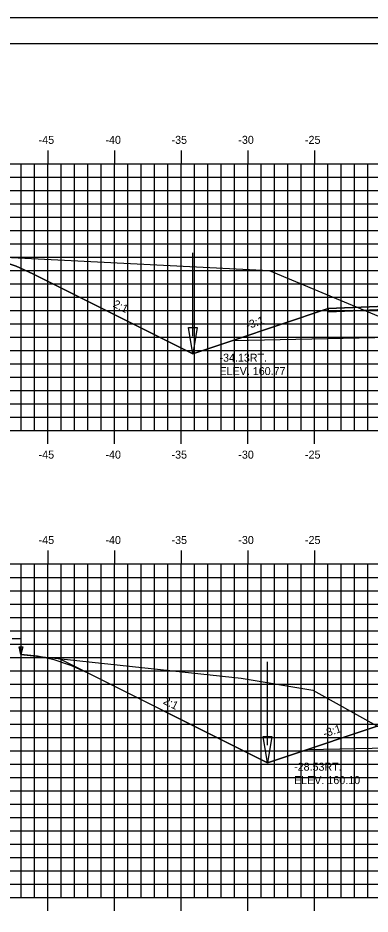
# Model space of a CAD drawing. Extents: x 1141424 to 1141594, y 608981 to 609091.
# Drawn here: x 1141460 to 1141486.4, y 609024.1 to 609091.3 of the extents above; entities that cross this region are included whole.
import ezdxf

# ---------------------------------------------------------------- set-up
doc = ezdxf.new("R2010")
doc.units = 0
for name, color, linetype in [('ANNOTATION', 7, 'Continuous'), ('BORDER', 7, 'Continuous'), ('D_Drainage_Ditch_Line', 7, 'Continuous'), ('D_Roadway_Edge_Shoulder', 7, 'Continuous'), ('D_Roadway_SlopeLines', 7, 'Continuous'), ('D_Roadway_SubGrade', 7, 'Continuous'), ('D_Text_Standard', 7, 'Continuous'), ('H_V ANNOTATION', 7, 'Continuous'), ('MAJOR', 7, 'Continuous'), ('MINOR', 7, 'Continuous'), ('PLOT BOUNDARY', 7, 'Continuous'), ('S_Roadway_Centerline', 7, 'Continuous')]:
    doc.layers.add(name, color=color, linetype=linetype)

msp = doc.modelspace()

# ---------------------------------------------------------------- linework, layer by layer
for points in [[(1141456.146, 609073.465), (1141457.396, 609073.337), (1141458.646, 609073.068), (1141459.896, 609072.656), (1141461.146, 609072.102), (1141473.145, 609066.102), (1141476.145, 609067.102), (1141483.295, 609069.486), (1141483.296, 609069.486), (1141496.271, 609070.005), (1141507.271, 609070.225), (1141518.271, 609070.005), (1141522.271, 609069.845), (1141529.994, 609067.271), (1141532.994, 609066.271), (1141540.103, 609069.825), (1141541.353, 609070.365), (1141542.603, 609070.736), (1141543.853, 609070.937), (1141545.103, 609070.968)], [(1141463.072, 609043.268), (1141478.738, 609035.436), (1141481.738, 609036.436), (1141489.27, 609038.946), (1141489.271, 609038.946), (1141496.271, 609039.226), (1141507.271, 609039.446), (1141518.271, 609039.226), (1141523.862, 609039.003), (1141531.484, 609036.462), (1141534.484, 609035.462), (1141535.293, 609035.192)]]:
    msp.add_lwpolyline(points)
at = {"layer": 'BORDER'}
msp.add_lwpolyline([(1141432.271, 608984.335), (1141592.271, 608984.335), (1141592.271, 609089.335), (1141432.271, 609089.335)], close=True, dxfattribs=at)
at = {"layer": 'D_Drainage_Ditch_Line'}
for p, q in [((1141473.145, 609067.415), (1141473.145, 609073.658)), ((1141478.738, 609036.748), (1141478.738, 609042.991))]:
    msp.add_line(p, q, dxfattribs=at)
for points in [[(1141472.817, 609068.071), (1141473.473, 609068.071), (1141473.145, 609066.102)], [(1141478.41, 609037.404), (1141479.066, 609037.404), (1141478.738, 609035.436)]]:
    msp.add_lwpolyline(points, close=True, dxfattribs=at)
at = {"layer": 'D_Roadway_Edge_Shoulder'}
msp.add_lwpolyline([(1141496.271, 609070.005), (1141483.296, 609069.486), (1141483.296, 609069.236), (1141496.271, 609069.755)], close=True, dxfattribs=at)
at = {"layer": 'D_Roadway_SlopeLines'}
for points in [[(1141473.145, 609066.102), (1141461.146, 609072.102), (1141459.896, 609072.656), (1141458.646, 609073.068), (1141457.396, 609073.337), (1141456.146, 609073.465)], [(1141476.145, 609067.102), (1141473.145, 609066.102)], [(1141478.738, 609035.436), (1141465.253, 609042.178), (1141464.003, 609042.732), (1141462.753, 609043.144), (1141461.503, 609043.413), (1141460.253, 609043.541)], [(1141481.738, 609036.436), (1141478.738, 609035.436)]]:
    msp.add_lwpolyline(points, dxfattribs=at)
at = {"layer": 'D_Roadway_SubGrade'}
for points in [[(1141496.271, 609069.588), (1141496.271, 609069.755), (1141483.296, 609069.236), (1141483.296, 609069.486), (1141483.295, 609069.486), (1141476.145, 609067.102), (1141496.271, 609067.505)], [(1141496.271, 609038.81), (1141496.271, 609038.976), (1141489.271, 609038.696), (1141489.271, 609038.946), (1141489.27, 609038.946), (1141481.738, 609036.436), (1141496.271, 609036.726)]]:
    msp.add_lwpolyline(points, close=True, dxfattribs=at)
at = {"layer": 'D_Text_Standard'}
msp.add_lwpolyline([(1141460.253, 609043.541), (1141460.282, 609044.715), (1141459.602, 609044.715)], dxfattribs=at)
msp.add_lwpolyline([(1141460.253, 609043.541), (1141460.122, 609044.126), (1141460.413, 609044.119)], close=True, dxfattribs=at)
at = {"layer": 'MAJOR'}
for p, q in [((1141462.271, 609081.337), (1141462.271, 609080.335)), ((1141467.271, 609081.337), (1141467.271, 609080.335)), ((1141472.271, 609081.337), (1141472.271, 609080.335)), ((1141477.271, 609081.337), (1141477.271, 609080.335)), ((1141482.271, 609081.337), (1141482.271, 609080.335)), ((1141437.271, 609080.335), (1141577.271, 609080.335)), ((1141437.271, 609080.335), (1141577.271, 609080.335)), ((1141462.271, 609060.335), (1141462.271, 609080.335)), ((1141467.271, 609060.335), (1141467.271, 609080.335)), ((1141472.271, 609060.335), (1141472.271, 609080.335)), ((1141477.271, 609060.335), (1141477.271, 609080.335)), ((1141482.271, 609060.335), (1141482.271, 609080.335)), ((1141437.271, 609075.335), (1141577.271, 609075.335)), ((1141437.271, 609070.335), (1141577.271, 609070.335)), ((1141437.271, 609065.335), (1141577.271, 609065.335)), ((1141437.271, 609060.335), (1141577.271, 609060.335)), ((1141437.271, 609060.335), (1141577.271, 609060.335)), ((1141462.271, 609059.333), (1141462.271, 609060.335)), ((1141467.271, 609059.333), (1141467.271, 609060.335)), ((1141472.271, 609059.333), (1141472.271, 609060.335)), ((1141477.271, 609059.333), (1141477.271, 609060.335)), ((1141482.271, 609059.333), (1141482.271, 609060.335)), ((1141462.271, 609051.337), (1141462.271, 609050.335)), ((1141467.271, 609051.337), (1141467.271, 609050.335)), ((1141472.271, 609051.337), (1141472.271, 609050.335)), ((1141477.271, 609051.337), (1141477.271, 609050.335)), ((1141482.271, 609051.337), (1141482.271, 609050.335)), ((1141437.271, 609050.335), (1141577.271, 609050.335)), ((1141437.271, 609050.335), (1141577.271, 609050.335)), ((1141462.271, 609025.335), (1141462.271, 609050.335)), ((1141467.271, 609025.335), (1141467.271, 609050.335)), ((1141472.271, 609025.335), (1141472.271, 609050.335)), ((1141477.271, 609025.335), (1141477.271, 609050.335)), ((1141482.271, 609025.335), (1141482.271, 609050.335)), ((1141437.271, 609045.335), (1141577.271, 609045.335)), ((1141437.271, 609040.335), (1141577.271, 609040.335)), ((1141437.271, 609035.335), (1141577.271, 609035.335)), ((1141437.271, 609030.335), (1141577.271, 609030.335)), ((1141437.271, 609025.335), (1141577.271, 609025.335)), ((1141437.271, 609025.335), (1141577.271, 609025.335)), ((1141462.271, 609024.333), (1141462.271, 609025.335)), ((1141467.271, 609024.333), (1141467.271, 609025.335)), ((1141472.271, 609024.333), (1141472.271, 609025.335)), ((1141477.271, 609024.333), (1141477.271, 609025.335)), ((1141482.271, 609024.333), (1141482.271, 609025.335))]:
    msp.add_line(p, q, dxfattribs=at)
at = {"layer": 'MINOR'}
for p, q in [((1141460.271, 609060.335), (1141460.271, 609080.335)), ((1141461.271, 609060.335), (1141461.271, 609080.335)), ((1141463.271, 609060.335), (1141463.271, 609080.335)), ((1141464.271, 609060.335), (1141464.271, 609080.335)), ((1141465.271, 609060.335), (1141465.271, 609080.335)), ((1141466.271, 609060.335), (1141466.271, 609080.335)), ((1141468.271, 609060.335), (1141468.271, 609080.335)), ((1141469.271, 609060.335), (1141469.271, 609080.335)), ((1141470.271, 609060.335), (1141470.271, 609080.335)), ((1141471.271, 609060.335), (1141471.271, 609080.335)), ((1141473.271, 609060.335), (1141473.271, 609080.335)), ((1141474.271, 609060.335), (1141474.271, 609080.335)), ((1141475.271, 609060.335), (1141475.271, 609080.335)), ((1141476.271, 609060.335), (1141476.271, 609080.335)), ((1141478.271, 609060.335), (1141478.271, 609080.335)), ((1141479.271, 609060.335), (1141479.271, 609080.335)), ((1141480.271, 609060.335), (1141480.271, 609080.335)), ((1141481.271, 609060.335), (1141481.271, 609080.335)), ((1141483.271, 609060.335), (1141483.271, 609080.335)), ((1141484.271, 609060.335), (1141484.271, 609080.335)), ((1141485.271, 609060.335), (1141485.271, 609080.335)), ((1141486.271, 609060.335), (1141486.271, 609080.335)), ((1141437.271, 609079.335), (1141577.271, 609079.335)), ((1141437.271, 609078.335), (1141577.271, 609078.335)), ((1141437.271, 609077.335), (1141577.271, 609077.335)), ((1141437.271, 609076.335), (1141577.271, 609076.335)), ((1141437.271, 609074.335), (1141577.271, 609074.335)), ((1141437.271, 609073.335), (1141577.271, 609073.335)), ((1141437.271, 609072.335), (1141577.271, 609072.335)), ((1141437.271, 609071.335), (1141577.271, 609071.335)), ((1141437.271, 609069.335), (1141577.271, 609069.335)), ((1141437.271, 609068.335), (1141577.271, 609068.335)), ((1141437.271, 609067.335), (1141577.271, 609067.335)), ((1141437.271, 609066.335), (1141577.271, 609066.335)), ((1141437.271, 609064.335), (1141577.271, 609064.335)), ((1141437.271, 609063.335), (1141577.271, 609063.335)), ((1141437.271, 609062.335), (1141577.271, 609062.335)), ((1141437.271, 609061.335), (1141577.271, 609061.335)), ((1141460.271, 609025.335), (1141460.271, 609050.335)), ((1141461.271, 609025.335), (1141461.271, 609050.335)), ((1141463.271, 609025.335), (1141463.271, 609050.335)), ((1141464.271, 609025.335), (1141464.271, 609050.335)), ((1141465.271, 609025.335), (1141465.271, 609050.335)), ((1141466.271, 609025.335), (1141466.271, 609050.335)), ((1141468.271, 609025.335), (1141468.271, 609050.335)), ((1141469.271, 609025.335), (1141469.271, 609050.335)), ((1141470.271, 609025.335), (1141470.271, 609050.335)), ((1141471.271, 609025.335), (1141471.271, 609050.335)), ((1141473.271, 609025.335), (1141473.271, 609050.335)), ((1141474.271, 609025.335), (1141474.271, 609050.335)), ((1141475.271, 609025.335), (1141475.271, 609050.335)), ((1141476.271, 609025.335), (1141476.271, 609050.335)), ((1141478.271, 609025.335), (1141478.271, 609050.335)), ((1141479.271, 609025.335), (1141479.271, 609050.335)), ((1141480.271, 609025.335), (1141480.271, 609050.335)), ((1141481.271, 609025.335), (1141481.271, 609050.335)), ((1141483.271, 609025.335), (1141483.271, 609050.335)), ((1141484.271, 609025.335), (1141484.271, 609050.335)), ((1141485.271, 609025.335), (1141485.271, 609050.335)), ((1141486.271, 609025.335), (1141486.271, 609050.335)), ((1141437.271, 609049.335), (1141577.271, 609049.335)), ((1141437.271, 609048.335), (1141577.271, 609048.335)), ((1141437.271, 609047.335), (1141577.271, 609047.335)), ((1141437.271, 609046.335), (1141577.271, 609046.335)), ((1141437.271, 609044.335), (1141577.271, 609044.335)), ((1141437.271, 609043.335), (1141577.271, 609043.335)), ((1141437.271, 609042.335), (1141577.271, 609042.335)), ((1141437.271, 609041.335), (1141577.271, 609041.335)), ((1141437.271, 609039.335), (1141577.271, 609039.335)), ((1141437.271, 609038.335), (1141577.271, 609038.335)), ((1141437.271, 609037.335), (1141577.271, 609037.335)), ((1141437.271, 609036.335), (1141577.271, 609036.335)), ((1141437.271, 609034.335), (1141577.271, 609034.335)), ((1141437.271, 609033.335), (1141577.271, 609033.335)), ((1141437.271, 609032.335), (1141577.271, 609032.335)), ((1141437.271, 609031.335), (1141577.271, 609031.335)), ((1141437.271, 609029.335), (1141577.271, 609029.335)), ((1141437.271, 609028.335), (1141577.271, 609028.335)), ((1141437.271, 609027.335), (1141577.271, 609027.335)), ((1141437.271, 609026.335), (1141577.271, 609026.335))]:
    msp.add_line(p, q, dxfattribs=at)
at = {"layer": 'PLOT BOUNDARY'}
msp.add_lwpolyline([(1141424.178, 608981.276), (1141594.178, 608981.276), (1141594.178, 609091.276), (1141424.178, 609091.276)], close=True, dxfattribs=at)
at = {"layer": 'S_Roadway_Centerline'}
for points in [[(1141454.537, 609073.535), (1141458.051, 609073.382), (1141478.858, 609072.336), (1141491.012, 609067.255), (1141491.392, 609067.105), (1141495.226, 609067.794), (1141495.325, 609067.825), (1141495.441, 609067.836), (1141498.174, 609068.166), (1141509.012, 609068.453), (1141509.602, 609068.468), (1141519.951, 609068.08), (1141520.424, 609068.064), (1141520.58, 609068.047), (1141523.884, 609067.752), (1141523.972, 609067.719), (1141527.544, 609066.625), (1141527.941, 609066.801), (1141535.037, 609071.404), (1141544.971, 609070.972), (1141552.331, 609070.764)], [(1141460.253, 609043.541), (1141476.77, 609041.777), (1141482.141, 609040.888), (1141491.527, 609035.647), (1141491.862, 609035.413), (1141494.612, 609035.718), (1141494.678, 609035.735), (1141496.776, 609036.013), (1141497.432, 609036.106), (1141508.706, 609036.443), (1141508.794, 609036.445), (1141517.825, 609036.227), (1141519.734, 609036.183), (1141519.739, 609036.182), (1141523.102, 609035.791), (1141523.112, 609035.787), (1141526.932, 609034.675), (1141527.029, 609034.645), (1141527.286, 609034.589), (1141536.73, 609035.3), (1141543.797, 609034.883), (1141551.696, 609034.212), (1141577.271, 609030.888)]]:
    msp.add_lwpolyline(points, dxfattribs=at)

# ---------------------------------------------------------------- texts
at = {"layer": 'ANNOTATION'}
for s, rotation, p in [('2:1', 333.43495, (1141467.112, 609069.637)), ('-3:1', 18.43483, (1141477.237, 609067.921)), ('2:1', 333.43495, (1141470.872, 609039.887)), ('-3:1', 18.43483, (1141483.021, 609037.317))]:
    msp.add_text(s, height=0.6, rotation=rotation, dxfattribs=at).set_placement(p)
at = {"layer": 'D_Text_Standard'}
for s, p in [('-34.13RT.', (1141475.145, 609065.502)), ('ELEV. 160.77', (1141475.145, 609064.5)), ('-28.53RT.', (1141480.738, 609034.836)), ('ELEV. 160.10', (1141480.738, 609033.834))]:
    msp.add_text(s, height=0.6, dxfattribs=at).set_placement(p)
at = {"layer": 'H_V ANNOTATION'}
for s, p in [('-45', (1141461.588, 609081.835)), ('-40', (1141466.596, 609081.835)), ('-35', (1141471.551, 609081.835)), ('-30', (1141476.559, 609081.835)), ('-25', (1141481.556, 609081.835)), ('-45', (1141461.588, 609058.235)), ('-40', (1141466.596, 609058.235)), ('-35', (1141471.551, 609058.235)), ('-30', (1141476.559, 609058.235)), ('-25', (1141481.556, 609058.235)), ('-45', (1141461.588, 609051.835)), ('-40', (1141466.596, 609051.835)), ('-35', (1141471.551, 609051.835)), ('-30', (1141476.559, 609051.835)), ('-25', (1141481.556, 609051.835))]:
    msp.add_text(s, height=0.6, dxfattribs=at).set_placement(p)

doc.saveas('drawing.dxf')
